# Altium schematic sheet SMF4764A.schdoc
size 127 x 101 mm
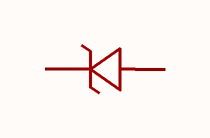
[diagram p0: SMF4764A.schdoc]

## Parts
D?  smf4764a  [SOD-123FL_L2.8-W1.9-LS3.7-RD]  (value not drawn)

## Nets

Not connected (* = marked no-connect by the designer): D? 1(C) 2(A)

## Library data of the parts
D? = smf4764a: 二极管配置:1个独立式;稳压值(标称值):100V;稳压值(范围值):95V~105V;耗散功率(Pd):1W;; Manufacturer: CJ(江苏长电/长晶); AddInBom: yes; ModelId: ee80cc4b5e2f4a0b8a944bbfc66c96ba; ModelTransform: 141.732,74.803,0,0,0,0,0,0,0; Diode Configuration: 1个独立式; Zener Voltage(Nom): 100V; Reverse Leakage Current (Ir): 100nA@76V; Pd - Power Dissipation: 1W; Impedance(Zzt): 350Ω; Impedance(Zzk): 3kΩ; Operating Junction Temperature Range: -55℃~+150℃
